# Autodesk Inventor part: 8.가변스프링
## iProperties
Created: 2015-04
Part Number: 8.가변스프링
Document SubType Name: Modeling
Designer: Administrator
Density: 1 g/cm^3
Mass: 0.615911 g
Surface Area: 12.573 cm^2
Volume: 0.615911 cm^3
Author: Administrator
